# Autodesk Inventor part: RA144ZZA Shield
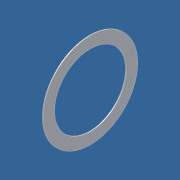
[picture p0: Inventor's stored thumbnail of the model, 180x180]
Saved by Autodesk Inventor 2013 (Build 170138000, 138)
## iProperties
Category: PARTsolutions
Created: 2011-07
Part Number: RA144ZZA Shield
Catalog Web Link: www.cadenas.de
Description: Six types s - Inch system sizes
Document SubType Name: Modeling
Designer: PARTsolutions
Density: 1 g/cm^3
Material: Générique
NB: RA144ZZA Shield
NN: Six types s
NT: Inch system sizes
NBSYN: RA144ZZA Shield
LINA: RA144ZZA Shield
SD: 3.175
D: 6.350
B: 2.380
B1: 2.779
D1: 7.52
D2: 7.52
C1: 0.58
C2: 0.79
R: 0.08
ORDER: RA144ZZA
CR: 284
COR: 96
CRF: 29
CORF: 10
LSG: 59000
LSO: 70000
MASS: 0.27
ORDER1: R144
WSS: RA144ZA
WDS: RA144ZZA
UTWF: FLR144
FORSS: FLRA144ZA
FORDS: FLRA144ZZA
DA1: 3.9
DA2: 4
DA: 5.5
RAS: 0.08
MASS1: 0.33
VERS: 3
X: 1.587
N: 9
O: 14.954
RB: 0.470
KT: DUMMY
SUPPLIER: NTN
ARTICLENO: RA144ZZA Shield
BOMINFO: RA144ZZA Shield
CREATOR: CADENAS GmbH
PSOL_IDENT_0: {\\10.0.0.251\ps_data\23d-libs\ntn\ball_roller_bearings\miniature_extra_small_bb\inch_system_sizes\i
PSOL_IDENT_1: ss_s.prj},180 {VTYP=3D},{NB=RA144ZZA Shield},{LINA=RA144ZZA Shield},{NN=Six types s},{DATE=11.12.200
PSOL_IDENT_2: 7 08:48:22},{GEOMDATE=02.04.2007 13:01:00},{VERSION=},{LINEID=16080},{LINESUBID=-1},{WBVAR=}  {NB=RA
PSOL_IDENT_3: 144ZZA Shield},{LINA=RA144ZZA Shield},{KT=DUMMY},{IDNR=},{SD=3.175},{D=6.350},{B=2.380},{B1=2.779},{
PSOL_IDENT_4: D1=7.52},{D2=7.52},{C1=0.58},{C2=0.79},{R=0.08},{ORDER=RA144ZZA},{CR=284},{COR=96},{CRF=29},{CORF=10
PSOL_IDENT_5: },{LSG=59000},{LSO=70000},{MASS=0.27},{ORDER1=R144},{WSS=RA144ZA},{WDS=RA144ZZA},{UTWF=FLR144},{FORS
PSOL_IDENT_6: S=FLRA144ZA},{FORDS=FLRA144ZZA},{DA1=3.9},{DA2=4},{DA=5.5},{RAS=0.08},{MASS1=0.33},{VERS=3},{X=1.587
PSOL_IDENT_7: 5},{N=9},{O=14.95425},{RB=0.4699}
Title: RA144ZZA Shield
Author: Cadenas PARTsolutions
Comments: Inch system sizes
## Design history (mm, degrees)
sketch "Sketch_1"
  geometry: L1 (-0.015, 0)-(-0.063, 0); L2 (-0.063, 2.096)-(-0.015, 2.096); L3 (-0.015, 2.096)-(-0.015, 2.769); L4 (-0.015, 2.769)-(-0.063, 2.769); L5 (-0.063, 2.769)-(-0.063, 2.096)
  constraints: 10 end point
revolve "Revolution1" sketch "Sketch_1" stored, may be unused: angle "d0" = 360 deg
node "iss_s_XY"
node "iss_s_YZ"
node "iss_s_ZX"
node "iss_s_X"
node "iss_s_Y"
node "iss_s_Z"
node "iss_s_Center"
node "Solide1"
node "Corps solides"
node "Corps surfaciques"
